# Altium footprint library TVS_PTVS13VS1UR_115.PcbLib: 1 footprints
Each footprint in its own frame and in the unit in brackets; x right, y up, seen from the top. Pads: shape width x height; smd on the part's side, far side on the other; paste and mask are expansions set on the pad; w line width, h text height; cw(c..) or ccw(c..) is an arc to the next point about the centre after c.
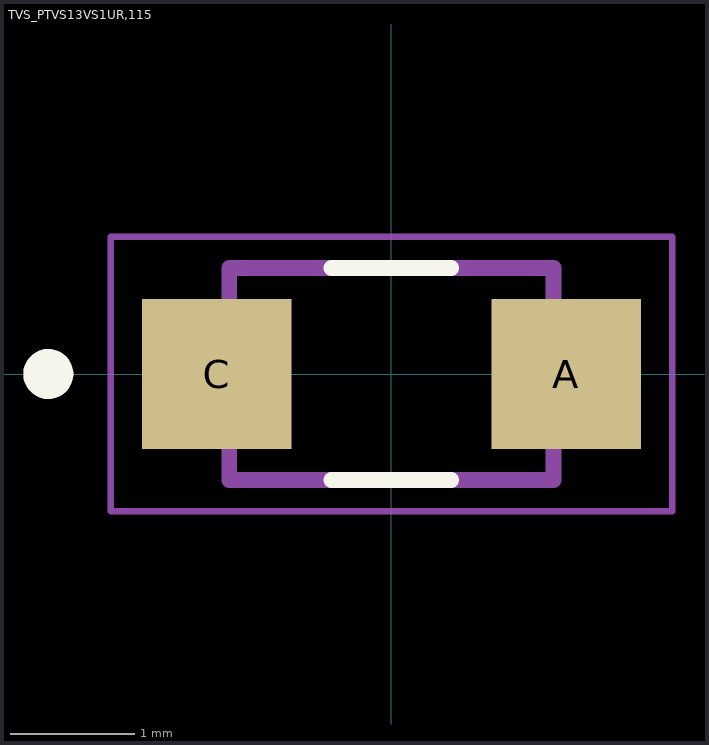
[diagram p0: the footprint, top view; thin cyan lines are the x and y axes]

## TVS_PTVS13VS1UR,115 [mm]
pads (2):
  rect 1.2x1.2 smd paste-0.05: A(1.4,0) C(-1.4,0)
Top Overlay:
  circle w0.2: c-2.75,0 r0.1
  lines w0.127: -0.48,-0.85 0.48,-0.85 ; -0.48,0.85 0.48,0.85
Mechanical 13:
  circle w0.2: c-2.75,0 r0.1
  lines w0.127: -1.3,-0.85 1.3,-0.85 1.3,0.85 -1.3,0.85 -1.3,-0.85
Mechanical 15:
  lines w0.05: -2.25,-1.1 2.25,-1.1 2.25,1.1 -2.25,1.1 -2.25,-1.1
3D body "step_temp.STEP": height 1.1, standoff 0, extent -1.75,-0.85 1.75,0.85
